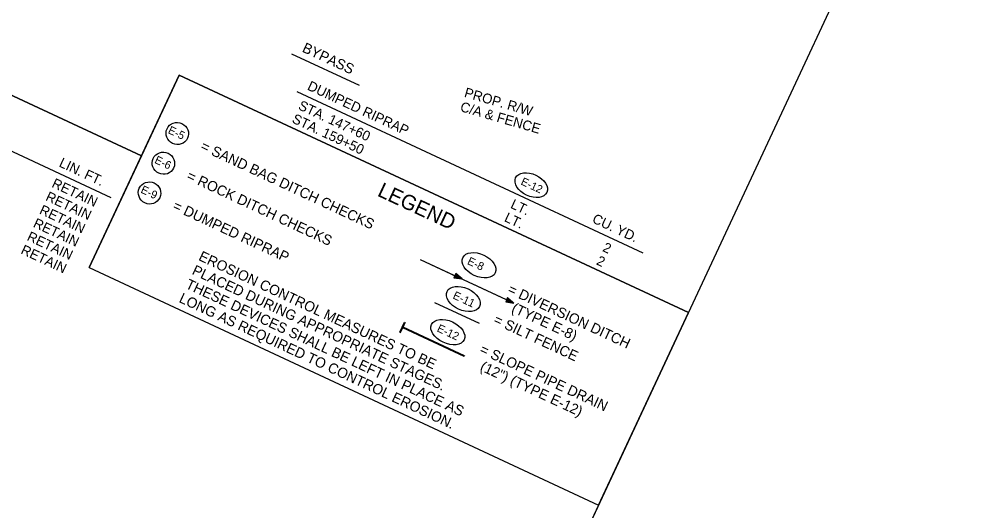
# Model space of a CAD drawing. Extents: x 980231 to 982096, y 1837566 to 1839185.
# Drawn here: x 981512 to 982096, y 1837967 to 1838266 of the extents above; entities that cross this region are included whole.
import ezdxf

# ---------------------------------------------------------------- set-up
doc = ezdxf.new("R2010")
doc.units = 0
for name, color, linetype in [('1', 7, 'Continuous'), ('44', 7, 'Continuous'), ('G-Border-Sheet', 7, 'Continuous'), ('Level 1', 7, 'Continuous'), ('Level 44', 7, 'Continuous'), ('R_Draft', 7, 'Continuous')]:
    doc.layers.add(name, color=color, linetype=linetype)

msp = doc.modelspace()

# ---------------------------------------------------------------- linework, layer by layer
at = {"layer": '1'}
for p, q in [((981756.38, 1838119.88), (981811.97, 1838093.96)), ((981778.18, 1838111.3), (981776.97, 1838108.67)), ((981776.97, 1838108.67), (981781.93, 1838107.96)), ((981777.12, 1838109.01), (981780.67, 1838108.23)), ((981777.28, 1838109.34), (981780.7, 1838108.32)), ((981777.43, 1838109.66), (981780.73, 1838108.42)), ((981780.81, 1838108.59), (981777.72, 1838110.31)), ((981780.86, 1838108.66), (981777.87, 1838110.63)), ((981780.92, 1838108.74), (981778.03, 1838110.96)), ((981781.93, 1838107.96), (981778.18, 1838111.3)), ((981809.73, 1838096.58), (981808.52, 1838093.96)), ((981812.47, 1838094.02), (981809.59, 1838096.25)), ((981813.48, 1838093.24), (981809.73, 1838096.58)), ((981808.52, 1838093.96), (981813.48, 1838093.24)), ((981808.67, 1838094.29), (981812.24, 1838093.52)), ((981808.83, 1838094.62), (981812.25, 1838093.61)), ((981808.98, 1838094.94), (981812.29, 1838093.69)), ((981812.37, 1838093.87), (981809.29, 1838095.6)), ((981812.42, 1838093.95), (981809.44, 1838095.92))]:
    msp.add_line(p, q, dxfattribs=at)
for points in [[(981756.37, 1838119.88), (981781.63, 1838108.1)], [(981787.94, 1838105.16), (981811.95, 1838093.96)]]:
    msp.add_lwpolyline(points, dxfattribs=at)
for centre, major_axis, ratio in [((981824.13, 1838165.18), (9.53, -4.45), 0.638788), ((981792.28, 1838116.33), (9.93, -4.63), 0.622952), ((981773.27, 1838075.56), (9.93, -4.63), 0.622952)]:
    msp.add_ellipse(centre, major_axis=major_axis, ratio=ratio, dxfattribs=at)
at = {"layer": '44'}
for p, q in [((981356.85, 1838256.01), (981567.84, 1838157.62)), ((981678, 1838245.33), (981719.3, 1838226.07)), ((981681.21, 1838222.21), (981892.2, 1838123.82)), ((981744.01, 1838075.57), (981746.85, 1838081.66)), ((981745.99, 1838078.63), (981747.3, 1838081.44)), ((981746.85, 1838081.66), (981747.3, 1838081.44)), ((981744.01, 1838075.57), (981744.46, 1838075.35)), ((981744.46, 1838075.35), (981745.78, 1838078.17)), ((981783.3, 1838060.67), (981745.78, 1838078.17)), ((981783.51, 1838061.13), (981745.99, 1838078.63)), ((981783.51, 1838061.13), (981783.3, 1838060.67))]:
    msp.add_line(p, q, dxfattribs=at)
at = {"layer": 'G-Border-Sheet'}
for p, q in [((980846.18, 1838528.31), (981586.46, 1838183.11)), ((981554.64, 1838114.87), (981609.41, 1838232.32)), ((981609.41, 1838232.32), (981919.96, 1838087.51)), ((981554.64, 1838114.87), (981865.2, 1837970.06)), ((981865.2, 1837970.06), (981919.96, 1838087.51))]:
    msp.add_line(p, q, dxfattribs=at)
for points in [[(980671.38, 1839184.86), (981846.87, 1838636.72), (981825.93, 1838591.82), (982096.33, 1838465.73), (981897.02, 1838038.3), (981897.02, 1838038.3), (981919.96, 1838087.51), (981609.41, 1838232.32), (981586.46, 1838183.11), (980846.18, 1838528.31), (980876.72, 1838593.79), (980491.54, 1838773.4), (980461.01, 1838707.92), (980451.13, 1838712.53)], [(980671.38, 1839184.86), (981846.87, 1838636.72), (981825.93, 1838591.82), (982096.33, 1838465.73), (981897.02, 1838038.3), (981897.02, 1838038.3), (981919.96, 1838087.51), (981609.41, 1838232.32), (981586.46, 1838183.11), (980846.18, 1838528.31), (980876.72, 1838593.79), (980491.54, 1838773.4), (980461.01, 1838707.92), (980451.13, 1838712.53)], [(980671.38, 1839184.86), (981846.87, 1838636.72), (981825.93, 1838591.82), (982096.33, 1838465.73), (981897.02, 1838038.3), (981897.02, 1838038.3), (981919.96, 1838087.51), (981609.41, 1838232.32), (981586.46, 1838183.11), (980846.18, 1838528.31), (980876.72, 1838593.79), (980491.54, 1838773.4), (980461.01, 1838707.92), (980451.13, 1838712.53)], [(980671.38, 1839184.86), (981846.87, 1838636.72), (981825.93, 1838591.82), (982096.33, 1838465.73), (981897.02, 1838038.3), (981897.02, 1838038.3), (981919.96, 1838087.51), (981609.41, 1838232.32), (981586.46, 1838183.11), (980846.18, 1838528.31), (980876.72, 1838593.79), (980491.54, 1838773.4), (980461.01, 1838707.92), (980451.13, 1838712.53)], [(981897.02, 1838038.3), (981676.77, 1837565.97), (981495.51, 1837650.49), (980230.88, 1838240.2), (980451.13, 1838712.53), (980461.01, 1838707.92), (980430.47, 1838642.44), (980815.65, 1838462.83), (980846.18, 1838528.31), (981586.46, 1838183.11), (981554.64, 1838114.87), (981865.2, 1837970.06), (981897.02, 1838038.3)], [(981897.02, 1838038.3), (981676.77, 1837565.97), (981495.51, 1837650.49), (980230.88, 1838240.2), (980451.13, 1838712.53), (980461.01, 1838707.92), (980430.47, 1838642.44), (980815.65, 1838462.83), (980846.18, 1838528.31), (981586.46, 1838183.11), (981554.64, 1838114.87), (981865.2, 1837970.06), (981897.02, 1838038.3)], [(981897.02, 1838038.3), (981676.77, 1837565.97), (981495.51, 1837650.49), (980230.88, 1838240.2), (980451.13, 1838712.53), (980461.01, 1838707.92), (980430.52, 1838642.55), (980815.7, 1838462.93), (980846.18, 1838528.31), (981586.46, 1838183.11), (981554.64, 1838114.87), (981865.2, 1837970.06), (981897.02, 1838038.3)], [(981897.02, 1838038.3), (981676.77, 1837565.97), (981495.51, 1837650.49), (980230.88, 1838240.2), (980450.96, 1838712.16), (980460.84, 1838707.56), (980430.52, 1838642.55), (980815.7, 1838462.93), (980846.18, 1838528.31), (981586.46, 1838183.11), (981554.64, 1838114.87), (981865.2, 1837970.06), (981897.02, 1838038.3)], [(981865.2, 1837970.06), (981676.77, 1837565.97), (981404.39, 1837692.98), (980230.88, 1838240.2), (980450.81, 1838711.85), (980460.69, 1838707.24), (980430.52, 1838642.55), (980815.7, 1838462.93), (980846.18, 1838528.31), (981586.46, 1838183.11), (981554.64, 1838114.87)]]:
    msp.add_lwpolyline(points, close=True, dxfattribs=at)
at = {"layer": 'Level 1'}
for centre, major_axis, ratio in [((981608.34, 1838196.66), (-6.24, 2.91), 0.97521), ((981599.88, 1838178.53), (-6.24, 2.91), 0.97521), ((981591.43, 1838160.41), (-6.24, 2.91), 0.97521), ((981782.69, 1838095.76), (9.93, -4.63), 0.622952)]:
    msp.add_ellipse(centre, major_axis=major_axis, ratio=ratio, dxfattribs=at)
at = {"layer": 'Level 44'}
msp.add_lwpolyline([(981765.1, 1838093.67), (981792.4, 1838080.95)], dxfattribs=at)

# ---------------------------------------------------------------- texts
at = {"layer": '1'}
for s, height, rotation, p in [('E-12', 4.8, 334.99998, (981817.34, 1838165.74)), ('E-8 ', 4.876, 335.00001, (981784.7, 1838117.21)), ('E-12', 4.876, 335.00001, (981766.21, 1838076.19))]:
    msp.add_text(s, height=height, rotation=rotation, dxfattribs=at).set_placement(p)
at = {"layer": '44'}
for s, height, rotation, p in [('BYPASS', 6.25, 335, (981683.99, 1838246.71)), ('DUMPED RIPRAP', 6, 334.99998, (981687.14, 1838223.59)), ('STA. 147+60', 6, 334.99998, (981681.58, 1838211.66)), ('STA. 159+50', 6, 334.99998, (981677.8, 1838203.55)), ('LIN. FT.', 6, 334.99998, (981535.76, 1838176.72)), ('RETAIN', 6, 334.99998, (981531.37, 1838164.23)), ('RETAIN', 6, 334.99998, (981527.59, 1838156.12)), ('LT.', 6, 334.99998, (981810.98, 1838151.48)), ('RETAIN', 6, 334.99998, (981523.81, 1838148.01)), ('RETAIN', 6, 334.99998, (981520.03, 1838139.9)), ('LT.', 6, 334.99998, (981807.2, 1838143.37)), ('CU. YD.', 6, 334.99998, (981860.77, 1838142.62)), ('RETAIN', 6, 334.99998, (981516.24, 1838131.79)), ('RETAIN', 6, 334.99998, (981512.46, 1838123.68)), ('2', 6, 334.99998, (981867.1, 1838125.13)), ('2', 6, 334.99998, (981863.32, 1838117.02))]:
    msp.add_text(s, height=height, rotation=rotation, dxfattribs=at).set_placement(p)
at = {"layer": 'Level 1'}
for s, height, p in [('E-5 ', 4.876, (981602.29, 1838197.03)), ('= SAND BAG DITCH CHECKS', 6.25, (981622, 1838186.84)), ('E-6 ', 4.876, (981594.07, 1838178.89)), ('= ROCK DITCH CHECKS', 6.25, (981613.54, 1838168.71)), ('E-9 ', 4.876, (981585.62, 1838160.77)), ('= DUMPED RIPRAP', 6.25, (981605.02, 1838150.47)), ('EROSION CONTROL MEASURES TO BE', 6.25, (981620.83, 1838119.65)), ('PLACED DURING APPROPRIATE STAGES. ', 6.25, (981616.85, 1838111.12)), ('THESE DEVICES SHALL BE LEFT IN PLACE AS ', 6.25, (981612.88, 1838102.59)), ('= DIVERSION DITCH', 6.25, (981809.22, 1838099.56)), ('LONG AS REQUIRED TO CONTROL EROSION.', 6.25, (981608.9, 1838094.06)), ('E-11 ', 4.876, (981775.88, 1838096.29)), ('   (TYPE E-8)', 6.25, (981805.26, 1838091.07)), ('= SILT FENCE', 6.25, (981800.58, 1838081.04)), ('= SLOPE PIPE DRAIN', 6.25, (981792.13, 1838062.92)), ('  (12") (TYPE E-12)', 6.25, (981788.17, 1838054.42))]:
    msp.add_text(s, height=height, rotation=335.00001, dxfattribs=at).set_placement(p)
at = {"layer": 'Level 44'}
msp.add_text('LEGEND', height=9.143, rotation=335.00001, dxfattribs=at).set_placement((981729.78, 1838158.87))
at = {"layer": 'R_Draft'}
for s, p in [('PROP. R/W', (981782.84, 1838219.05)), ('C/A & FENCE', (981780.34, 1838210.4))]:
    msp.add_text(s, height=6, rotation=343.89378, dxfattribs=at).set_placement(p)

doc.saveas('drawing.dxf')
